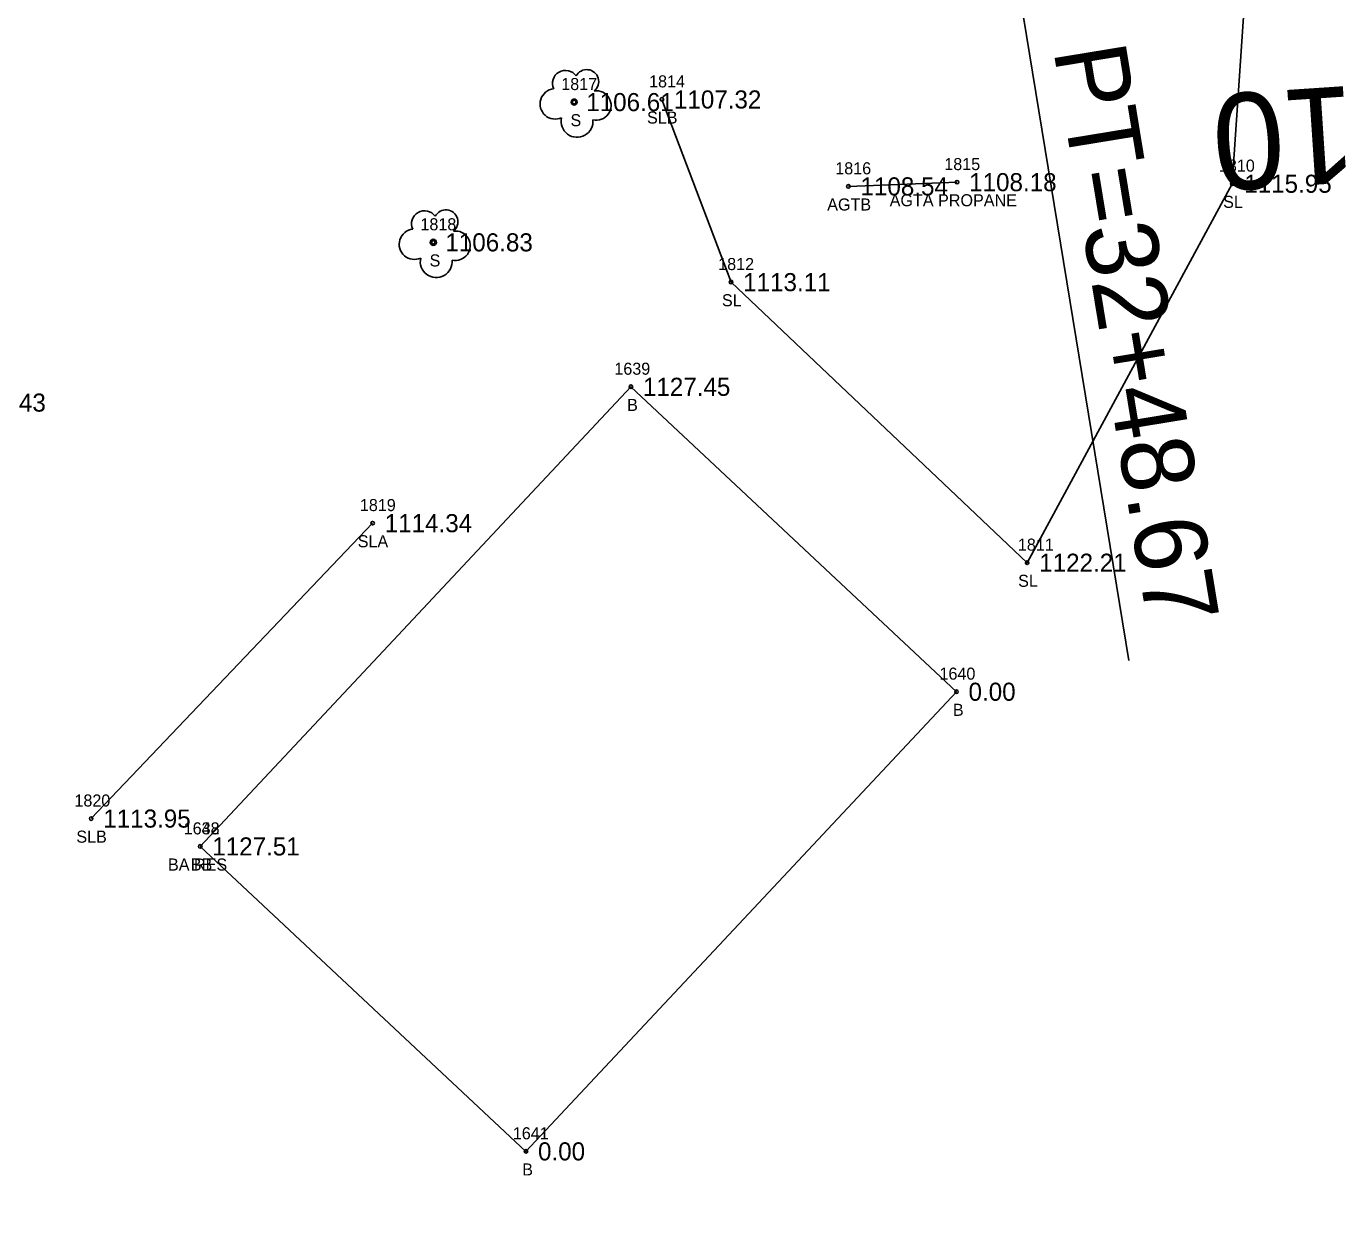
# Model space of a CAD drawing. Extents: x 1539151 to 1541799, y 1198646 to 1201165.
# Drawn here: x 1541156.3 to 1541265.6, y 1200262.8 to 1200361.6 of the extents above; entities that cross this region are included whole.
import ezdxf

# ---------------------------------------------------------------- set-up
doc = ezdxf.new("R2010")
doc.units = 0
for name, color, linetype in [('RD_EX_Bldg', 7, 'Continuous'), ('RD_EX_Bldg_txCode', 7, 'Continuous'), ('RD_EX_BldgApp', 7, 'Continuous'), ('RD_EX_BldgApp_txCode', 7, 'Continuous'), ('RD_EX_TX_Bldg_ELEV', 7, 'Continuous'), ('RD_EX_TX_BldgApp_ELEV', 7, 'Continuous'), ('RD_EX_TX_VEG_ELEV', 7, 'Continuous'), ('RD_EX_VEG', 7, 'Continuous'), ('RD_EX_VEG_txCode', 7, 'Continuous'), ('RD_HC_Cl', 7, 'Continuous'), ('RD_HC_Data', 7, 'Continuous'), ('RD_HC_TX_Sta50', 7, 'Continuous'), ('RD_SMD_Locator', 7, 'Continuous')]:
    doc.layers.add(name, color=color, linetype=linetype)

msp = doc.modelspace()

# ---------------------------------------------------------------- linework, layer by layer
at = {"layer": 'RD_EX_Bldg'}
msp.add_lwpolyline([(1541170.67, 1200293.62), (1541206.38, 1200331.74), (1541233.38, 1200306.45), (1541197.68, 1200268.33), (1541170.67, 1200293.62)], dxfattribs=at)
at = {"layer": 'RD_EX_BldgApp'}
msp.add_line((1541233.43, 1200348.71), (1541224.42, 1200348.36), dxfattribs=at)
at = {"layer": 'RD_EX_VEG'}
msp.add_line((1541184.97, 1200320.43), (1541161.63, 1200295.93), dxfattribs=at)
msp.add_lwpolyline([(1541254.36, 1200396.03), (1541257.61, 1200368.98), (1541256.24, 1200348.58), (1541239.24, 1200317.15), (1541214.69, 1200340.42), (1541208.95, 1200355.57)], dxfattribs=at)
for centre in [(1541201.68, 1200355.35), (1541190, 1200343.72)]:
    msp.add_circle(centre, 0.25, dxfattribs=at)
for centre, radius, start, end in [((1541200.96, 1200356.9), 1.08, 34.9763, 204.756), ((1541202.72, 1200357.05), 0.995, 308.7626, 152.0467), ((1541200.11, 1200355.2), 1.26, 96.4518, 294.734), ((1541203.52, 1200355.07), 1.22, 256.5667, 98.1046), ((1541201.92, 1200353.75), 1.32, 166.8827, 5.7589), ((1541189.27, 1200345.26), 1.08, 34.9763, 204.756), ((1541191.04, 1200345.42), 0.995, 308.7626, 152.0467), ((1541188.43, 1200343.56), 1.26, 96.4518, 294.734), ((1541191.84, 1200343.44), 1.22, 256.5667, 98.1046), ((1541190.24, 1200342.12), 1.32, 166.8827, 5.7589)]:
    msp.add_arc(centre, radius, start, end, dxfattribs=at)
at = {"layer": 'RD_HC_Cl'}
msp.add_arc((1541347.27, 1199701.68), 731.44, 99.31232, 138.32753, dxfattribs=at)
at = {"layer": 'RD_HC_Data'}
msp.add_line((1541228.92, 1200423.48), (1541247.68, 1200309.05), dxfattribs=at)
at = {"layer": 'RD_SMD_Locator'}
for centre in [(1541201.68, 1200355.35), (1541208.95, 1200355.57), (1541224.42, 1200348.36), (1541233.43, 1200348.71), (1541256.24, 1200348.58), (1541190, 1200343.72), (1541214.69, 1200340.42), (1541206.38, 1200331.74), (1541184.97, 1200320.43), (1541239.24, 1200317.15), (1541233.38, 1200306.45), (1541161.63, 1200295.93), (1541170.67, 1200293.62), (1541170.67, 1200293.62), (1541197.68, 1200268.33)]:
    msp.add_circle(centre, 0.15, dxfattribs=at)

# ---------------------------------------------------------------- texts
at = {"layer": 'RD_EX_Bldg_txCode'}
for s, p in [('1639', (1541205.01, 1200332.74)), ('B', (1541206.07, 1200329.74)), ('1640', (1541231.97, 1200307.45)), ('B', (1541233.08, 1200304.45)), ('1638', (1541169.3, 1200294.62)), ('1642', (1541169.3, 1200294.62)), ('BA RES', (1541168, 1200291.62)), ('BB', (1541169.89, 1200291.62)), ('1641', (1541196.59, 1200269.33)), ('B', (1541197.37, 1200266.33))]:
    msp.add_text(s, height=1, dxfattribs=at).set_placement(p)
at = {"layer": 'RD_EX_BldgApp_txCode'}
for s, p in [('1816', (1541223.33, 1200349.36)), ('1815', (1541232.37, 1200349.71)), ('AGTB', (1541222.66, 1200346.36)), ('AGTA PROPANE', (1541227.84, 1200346.71))]:
    msp.add_text(s, height=1, dxfattribs=at).set_placement(p)
at = {"layer": 'RD_EX_TX_Bldg_ELEV'}
for s, p in [('1127.45', (1541207.38, 1200330.99)), ('0.00', (1541234.38, 1200305.7)), ('1127.51', (1541171.67, 1200292.87)), ('1127.51', (1541171.67, 1200292.87)), ('0.00', (1541198.68, 1200267.58))]:
    msp.add_text(s, height=1.5, dxfattribs=at).set_placement(p)
at = {"layer": 'RD_EX_TX_BldgApp_ELEV'}
for s, p in [('1108.54', (1541225.42, 1200347.61)), ('1108.18', (1541234.43, 1200347.96))]:
    msp.add_text(s, height=1.5, dxfattribs=at).set_placement(p)
at = {"layer": 'RD_EX_TX_VEG_ELEV'}
for s, p in [('1106.61', (1541202.68, 1200354.6)), ('1107.32', (1541209.95, 1200354.82)), ('1115.95', (1541257.24, 1200347.83)), ('1106.83', (1541191, 1200342.97)), ('1113.11', (1541215.69, 1200339.67)), ('1104.43', (1541150.62, 1200329.68)), ('1114.34', (1541185.97, 1200319.68)), ('1122.21', (1541240.24, 1200316.4)), ('1113.95', (1541162.63, 1200295.18))]:
    msp.add_text(s, height=1.5, dxfattribs=at).set_placement(p)
at = {"layer": 'RD_EX_VEG_txCode'}
for s, p in [('1817', (1541200.61, 1200356.35)), ('1814', (1541207.89, 1200356.57)), ('S', (1541201.37, 1200353.35)), ('SLB', (1541207.72, 1200353.57)), ('1810', (1541255.14, 1200349.58)), ('SL', (1541255.49, 1200346.58)), ('1818', (1541188.93, 1200344.72)), ('S', (1541189.69, 1200341.72)), ('1812', (1541213.62, 1200341.42)), ('SL', (1541213.93, 1200338.42)), ('1819', (1541183.91, 1200321.43)), ('SLA', (1541183.73, 1200318.43)), ('1811', (1541238.47, 1200318.15)), ('SL', (1541238.49, 1200315.15)), ('1820', (1541160.24, 1200296.93)), ('SLB', (1541160.4, 1200293.93))]:
    msp.add_text(s, height=1, dxfattribs=at).set_placement(p)
at = {"layer": 'RD_HC_Data'}
msp.add_text('PT=32+48.67', height=6, rotation=279.3123, dxfattribs=at).set_placement((1541241.41, 1200359.66))
at = {"layer": 'RD_HC_TX_Sta50'}
msp.add_text('10', height=8, rotation=183.8059, dxfattribs=at).set_placement((1541266.23, 1200356.72))

doc.saveas('drawing.dxf')
